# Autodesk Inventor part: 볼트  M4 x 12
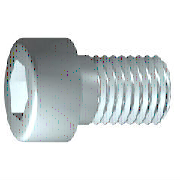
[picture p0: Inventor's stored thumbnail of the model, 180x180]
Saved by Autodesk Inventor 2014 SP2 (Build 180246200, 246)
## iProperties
IsCustomPart: 0
Created: 2015-12
Part Number: 볼트  M4 x 12
Material: 일반
Description: 6각머리 태핑 나사
Document SubType Name: Modeling
Standard: KS B 1003
Designer: mdu
Standards Organization: KS
Language: ko-KR
Size Designation: M 4 x 12
Categories: <MemberInstance><Categories><Category DisplayName="조임쇠" InternalName="e4da775c-781d-43d5-af7c-5136215cf5a6" Mnemonic="FSTN"><Category DisplayName="볼트" InternalN
Density: 1 g/cm^3
Mass: 0.284306 g
Surface Area: 3.30853 cm^2
Volume: 0.284306 cm^3
Appearance: 기본값
Author: mdu
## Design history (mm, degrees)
sketch "스케치1"
  geometry: L1 (-1, 0)-(12, 0); L2 (12, 0)-(12, 2); L3 (12, 2)-(1.75, 2); L4 (1.75, 2)-(1.32, 2); L5 (1.32, 2)-(0, 2); L6 (0, 2)-(0, 3.5); L7 (0, 3.5)-(-4, 3.5); L8 (-4, 3.5)-(-4, 1.732); L9 (-4, 1.732)-(-2, 1.732); L10 (-2, 1.732)-(-1, 0); L11 (-7.2, 0)-(15.2, 0) reference; L12 (0, -0.7)-(0, 4.2) reference; L13 (1.75, 2)-(0, 2)
  constraints: 22 end point, 6 parallel, 2 collinear, 2 perpendicular, 1 horizontal, 1 point on line
  dimensions: "d1" = 10.25 distance from line of L3.end L2 (= GEL); "d2" = 0.42952 distance of L4.end L3.end (computed from GAL); "d3" = 4 distance between parallel lines of L8 L6 (= KOH); "d4" = 2 distance of L8.end L9.end (= INTI); "d5" = 60 deg angle of L10 L1; "d6" = 4 diameter of L3 L1 (= GD); "d7" = 4 diameter of L5 L1 (= BDM); "d8" = 3.4641 diameter of L9 L1 (= 1.1547 x SW); "d9" = 7 diameter of L7 L1 (= KOD); "d26" = 12 distance between parallel lines of L12 L2 (= NLG)
revolve "본체" sketch "스케치1" stored, may be unused: angle "d10" = 90 deg
sketch "스케치2"
  geometry: L1 (0, -4.9)-(0, 4.9) reference; L2 (-4.9, 0)-(4.9, 0) reference; L3 (1.732, 0)-(0.866, -1.5); L4 (0.866, -1.5)-(-0.866, -1.5); L5 (-0.866, -1.5)-(-1.732, 0); L6 (-1.732, 0)-(-0.866, 1.5); L7 (-0.866, 1.5)-(0.866, 1.5); L8 (0.866, 1.5)-(1.732, 0); 2 further points
  constraints: 12 end point, 1 coincident, 1 horizontal alignment, 1 point on line, 12 other
extrude "슬롯" join sketch "스케치2" stored distance "d11" = 10; taper "d12" = 0 deg
workplane "Work Plane1"
fillet "Fillet2" dims "d30" = 0.1 (= R)
body "Solid1"
fillet "모깎기1" dims "d17" = 0.4 (= RR)
feature "스레드" dims "d13" = 10.25 (= GEL), "d14" = 0
chamfer "모따기1" distance "d15" = 0.42941 (= -0.5 x SPD + 0.5 x GD); stored, may be unused: second distance "d16" = 0.42941 (= GUL), angle "d27" = 45 deg
other parameters: "GD" = 4 (= NND) [user parameter; used in 2 equation terms], "NLG" = 12 [user parameter; used in 1 equation term], "GEL" = 10.25 [user parameter; used in 2 equation terms], "KOD" = 7 [user parameter; used in 1 equation term], "KOH" = 4 [user parameter; used in 1 equation term], "INTI" = 2 [user parameter; used in 1 equation term], "GAL" = 0.42941 (= 0.61345 x PTC) [user parameter; used in 1 equation term], "GUL" = 0.42941 (= 0.61345 x PTC) [user parameter; used in 1 equation term], "BDM" = 4 (= NND) [user parameter; used in 1 equation term], "SW" = 3 [user parameter; used in 2 equation terms], "RR" = 0.4 [user parameter; used in 1 equation term], "SPD" = 3.14117 (= NND - 1.2269 x PTC) [user parameter; used in 1 equation term], "d19" = 0, "d28" = 0, "d29" = 0, "R" = 0.1 [user parameter; used in 1 equation term], "PHH" = 0.2 [user parameter], "GD1" = 3.14117 (= THREADDIA - 1.2269 x PTC) [user parameter], "THREADDIA" = 4 [user parameter; used in 1 equation term], "FAWI" = 45 deg [user parameter], "TPU" = 14.28571 (computed from PTC) [user parameter], "PTC" = 0.7 [user parameter; used in 5 equation terms], "NND" = 4 [user parameter; used in 3 equation terms], "TOA" = 30 deg [user parameter], "E0" = 3.465 (= 1.155 x SW) [user parameter]
